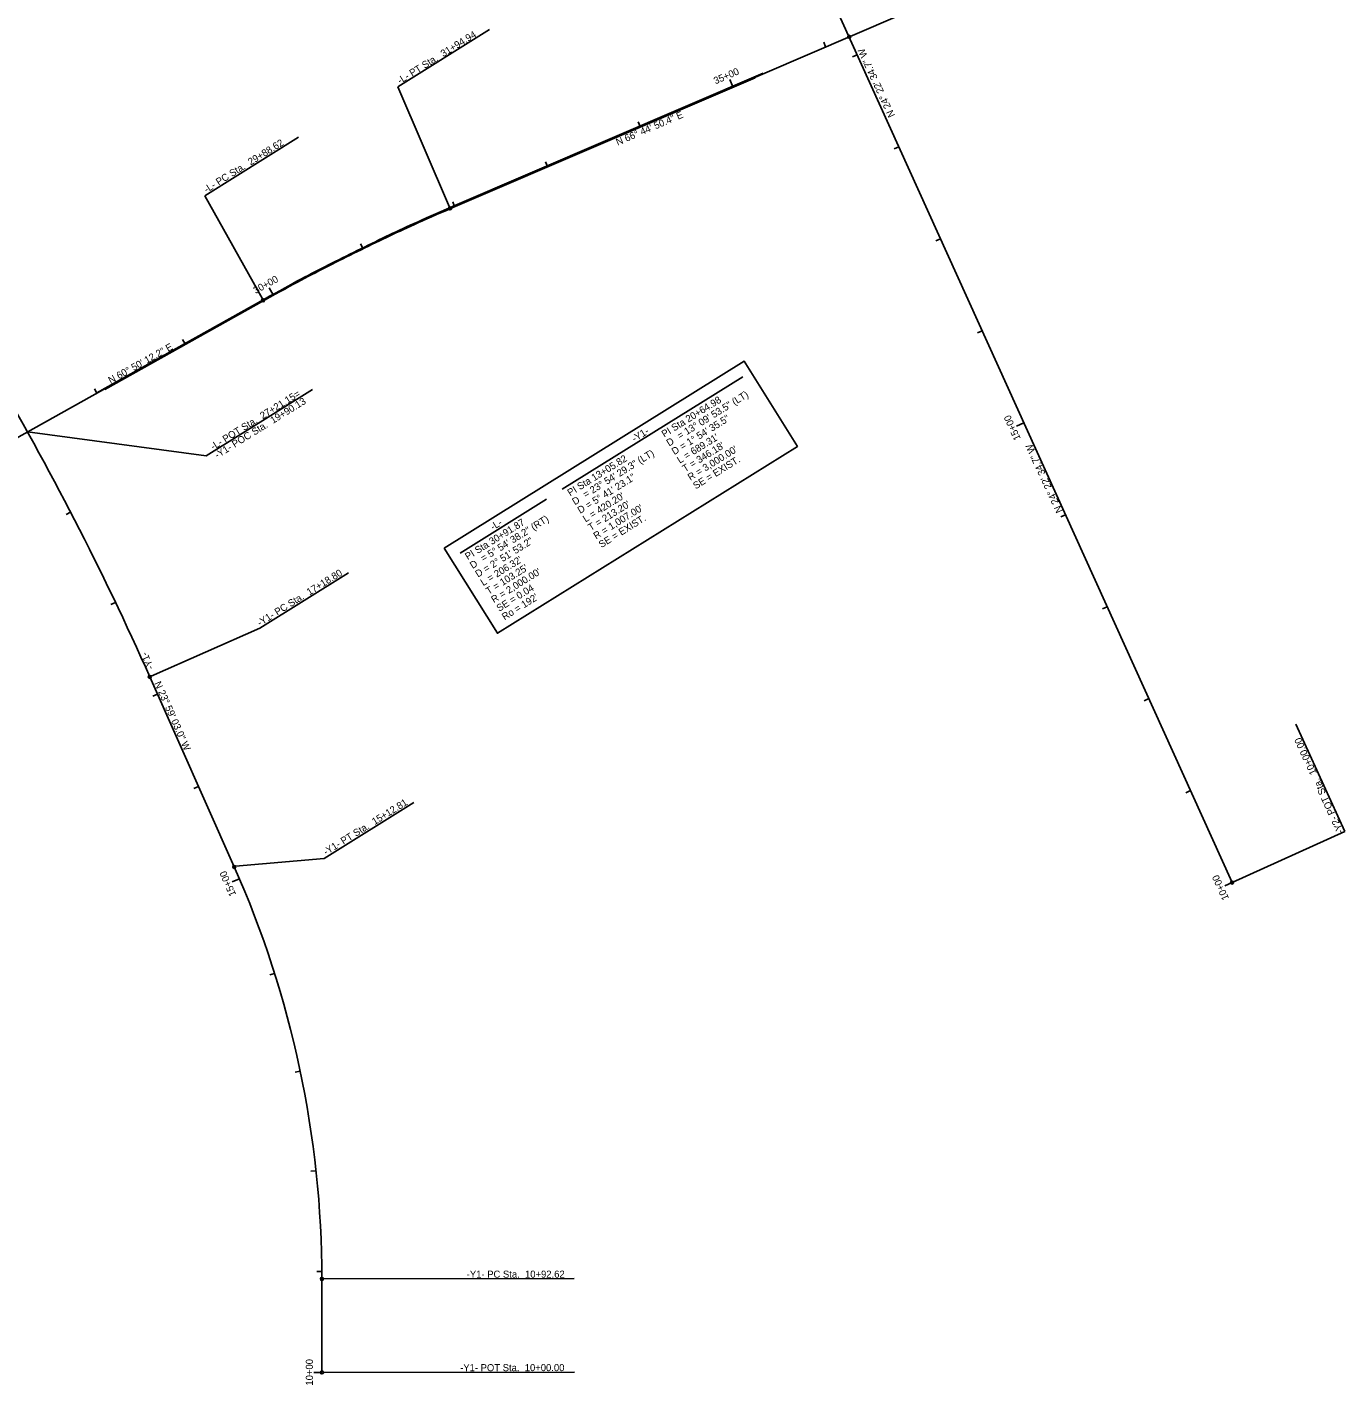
# Model space of a CAD drawing. Extents: x 2045940 to 2048976, y 757914 to 760106.
# Drawn here: x 2047500 to 2048806, y 757914 to 759259 of the extents above; entities that cross this region are included whole.
import ezdxf

# ---------------------------------------------------------------- set-up
doc = ezdxf.new("R2010")
doc.units = 0
for name, color, linetype in [('Prop AutoTurn Projected Path', 7, 'Continuous'), ('Prop Conc 1ft 6in Curb and Gutter', 7, 'Continuous'), ('Prop Conc 5in Monolithic Surface Mount Island', 7, 'Continuous'), ('Prop Dimension', 7, 'Continuous'), ('Prop Horizontal Alignment', 7, 'Continuous'), ('Prop Lane Lines', 7, 'Continuous'), ('Prop Superelevation  Arrow CELL', 7, 'Continuous'), ('Prop Superelevation Label', 7, 'Continuous'), ('Prop Terminator CELL', 7, 'Continuous'), ('Typical Terminator CELL', 7, 'Continuous')]:
    doc.layers.add(name, color=color, linetype=linetype)

msp = doc.modelspace()

# ---------------------------------------------------------------- linework, layer by layer
at = {"layer": 'Prop AutoTurn Projected Path'}
for p, q in [((2048030.6, 758801.4), (2048209.5, 758912.8)), ((2047929.3, 758738.3), (2048014.8, 758791.5))]:
    msp.add_line(p, q, dxfattribs=at)
at = {"layer": 'Prop Conc 1ft 6in Curb and Gutter'}
for p, q in [((2047867.5, 759200.1), (2047958.6, 759256.8)), ((2047918.7, 759081), (2047867.5, 759200.1)), ((2047676.4, 759092.2), (2047769.4, 759150.1)), ((2047733.5, 758989.9), (2047676.4, 759092.2)), ((2047677.9, 758834.6), (2047783.1, 758900.1)), ((2047677.9, 758834.6), (2047500.7, 758858.2)), ((2047730.8, 758664), (2047818.7, 758718.7)), ((2047623.3, 758616.2), (2047730.8, 758664)), ((2048805.8, 758462.5), (2048757.1, 758568.8)), ((2047794.7, 758435.9), (2047883.6, 758491.3)), ((2048694.1, 758411.9), (2048805.8, 758462.5)), ((2047707, 758428), (2047794.7, 758435.9)), ((2047793.9, 758019.3), (2048042.4, 758019.6)), ((2047794, 757926.7), (2048042.5, 757927))]:
    msp.add_line(p, q, dxfattribs=at)
for centre in [(2048314.8, 759249.6), (2047919.3, 759079.6), (2047734.2, 758988.6), (2047621.9, 758615.6), (2047705.6, 758427.4), (2048694.1, 758411.9), (2048694.1, 758411.9), (2047792.4, 758019.3), (2047792.5, 757926.7)]:
    msp.add_circle(centre, 1.5, dxfattribs=at)
at = {"layer": 'Prop Dimension'}
for p, q in [((2048199.6, 759200.1), (2048196.4, 759207.4)), ((2047744.2, 758994.1), (2047740.3, 759001.1)), ((2048487.7, 758867.3), (2048480.4, 758864)), ((2047710.7, 758415.6), (2047703.4, 758412.5)), ((2048694.1, 758411.9), (2048686.8, 758408.6)), ((2047792.5, 757926.7), (2047784.5, 757926.7))]:
    msp.add_line(p, q, dxfattribs=at)
at = {"layer": 'Prop Horizontal Alignment'}
for p, q in [((2048694.1, 758411.9), (2048082.8, 759761)), ((2047919.3, 759079.6), (2048475.2, 759318.5)), ((2047322, 758758.5), (2047734.2, 758988.6)), ((2047705.6, 758427.4), (2047621.9, 758615.6)), ((2047705.6, 758427.4), (2047621.9, 758615.6)), ((2047792.5, 757926.7), (2047792.4, 758019.3)), ((2047792.5, 757926.7), (2047792.4, 758019.3))]:
    msp.add_line(p, q, dxfattribs=at)
for centre, radius, start, end in [((2044880.6, 757397.1), 3000, 23.9646, 37.1294), ((2044880.6, 757397.1), 3000, 23.9646, 37.1294), ((2048708.8, 757242.1), 2000, 113.2527, 119.1633), ((2046785.4, 758018.4), 1007, 0.0564, 23.9646), ((2046785.4, 758018.4), 1007, 0.0564, 23.9646)]:
    msp.add_arc(centre, radius, start, end, dxfattribs=at)
at = {"layer": 'Prop Superelevation  Arrow CELL'}
for p, q in [((2047921.8, 759081.4), (2048229.4, 759213.5)), ((2047569.4, 758896.9), (2047735, 758989.5))]:
    msp.add_line(p, q, dxfattribs=at)
msp.add_open_spline([(2047735, 758989.5), (2047765.4, 759006.4), (2047796.1, 759022.5), (2047858.4, 759053.2), (2047889.9, 759067.7), (2047921.8, 759081.4)], degree=3, dxfattribs=at)
at = {"layer": 'Prop Superelevation Label'}
msp.add_lwpolyline([(2047913.7, 758743.2), (2048210.9, 758928.3), (2048263.5, 758843.9), (2047966.3, 758658.8)], close=True, dxfattribs=at)
at = {"layer": 'Prop Terminator CELL'}
for p, q in [((2048291.4, 759239.6), (2048289.5, 759244.1)), ((2048322.6, 759231.7), (2048318.1, 759229.6)), ((2048107.7, 759160.6), (2048105.7, 759165.2)), ((2048363.9, 759140.6), (2048359.3, 759138.5)), ((2048015.8, 759121.1), (2048013.8, 759125.7)), ((2047923.9, 759081.6), (2047922, 759086.2)), ((2048405.2, 759049.5), (2048400.6, 759047.4)), ((2047833, 759040.1), (2047830.8, 759044.6)), ((2048446.4, 758958.4), (2048441.9, 758956.3)), ((2047656.9, 758945.4), (2047654.4, 758949.7)), ((2047569.5, 758896.6), (2047567.1, 758901)), ((2047543.4, 758778.9), (2047539, 758776.6)), ((2048529, 758776.2), (2048524.4, 758774.2)), ((2047588, 758689.3), (2047583.4, 758687.2)), ((2048570.2, 758685.1), (2048565.7, 758683.1)), ((2047629.6, 758598.4), (2047625, 758596.4)), ((2048611.5, 758594.1), (2048607, 758592)), ((2047670.2, 758507), (2047665.6, 758505)), ((2048652.8, 758503), (2048648.2, 758500.9)), ((2047745.6, 758321.9), (2047740.8, 758320.4)), ((2047770.9, 758225.2), (2047766, 758224.2)), ((2047786.6, 758126.5), (2047781.6, 758126)), ((2047792.4, 758026.7), (2047787.4, 758026.7))]:
    msp.add_line(p, q, dxfattribs=at)
at = {"layer": 'Typical Terminator CELL'}
for p, q in [((2047922.2, 759080.5), (2048221.5, 759209)), ((2047577.5, 758900.3), (2047735.5, 758988.6))]:
    msp.add_line(p, q, dxfattribs=at)
msp.add_open_spline([(2047735.5, 758988.6), (2047765.8, 759005.5), (2047796.6, 759021.7), (2047858.8, 759052.3), (2047890.3, 759066.8), (2047922.2, 759080.5)], degree=3, dxfattribs=at)

# ---------------------------------------------------------------- texts
at = {"layer": 'Prop AutoTurn Projected Path'}
for s, rotation, p in [('= 13%%d 09\' 53.5" (LT)', 31.9183, (2048147.1, 758850.7)), ('PI Sta 20+64.98', 31.9183, (2048131.6, 758852.5)), ('D = 1%%d 54\' 35.5"', 31.9183, (2048141.6, 758835.2)), ('-Y1-', 31.9194, (2048102.1, 758847.9)), ('D', 31.9183, (2048136.4, 758843.7)), ("L = 689.31'", 31.9183, (2048146.9, 758826.7)), ("T = 346.18'", 31.9183, (2048152.2, 758818.2)), ("R = 3,000.00'", 31.9183, (2048157.5, 758809.7)), ('PI Sta 13+05.82', 31.9183, (2048038.3, 758794.4)), ('= 23%%d 54\' 29.3" (LT)', 31.9183, (2048053.7, 758792.6)), ('SE = EXIST.', 31.9194, (2048162.8, 758801.2)), ('D = 5%%d 41\' 23.1"', 31.9183, (2048048.3, 758777)), ('D', 31.9183, (2048043, 758785.5)), ("L = 420.20'", 31.9183, (2048053.6, 758768.5)), ("T = 213.20'", 31.9183, (2048058.8, 758760)), ("R = 1,007.00'", 31.9183, (2048064.1, 758751.6)), ('PI Sta 30+91.87', 31.9194, (2047936.9, 758731.2)), ('= 5%%d 54\' 38.2" (RT)', 31.9194, (2047952.4, 758729.4)), ('-L-', 31.9194, (2047962, 758760.6)), ('SE = EXIST.', 31.9194, (2048069.4, 758743.1)), ('D = 2%%d 51\' 53.2"', 31.9194, (2047947, 758713.9)), ('D', 31.9194, (2047941.7, 758722.4)), ("L = 206.32'", 31.9194, (2047952.2, 758705.4)), ("T = 103.25'", 31.9194, (2047957.5, 758696.9)), ("R = 2,000.00'", 31.9194, (2047962.8, 758688.5)), ('SE = 0.04', 31.9194, (2047968.1, 758680)), ("Ro = 192'", 31.9194, (2047973.4, 758671.5))]:
    msp.add_text(s, height=7, rotation=rotation, dxfattribs=at).set_placement(p)
at = {"layer": 'Prop Conc 1ft 6in Curb and Gutter'}
for s, rotation, p in [('-L- PT Sta.  31+94.94', 31.9194, (2047869.9, 759202.6)), ('-L- PC Sta.  29+88.62', 31.9194, (2047678.2, 759094.8)), ('-L- POT Sta.  27+21.15=', 31.9109, (2047684.8, 758840.1)), ('-Y1- POC Sta.  19+90.13', 31.9109, (2047688.8, 758831.7)), ('-Y1- PC Sta.  17+18.80', 31.9183, (2047731, 758665.5)), ('-Y2- POT Sta.  10+00.00', 114.6102, (2048804.8, 758462.3)), ('-Y1- PT Sta.  15+12.81', 31.9183, (2047796.5, 758438.7)), ('-Y1- PC Sta.  10+92.62', 0.0564, (2047935.9, 758020.5)), ('-Y1- POT Sta.  10+00.00', 0.0564, (2047929.4, 757927.9))]:
    msp.add_text(s, height=7, rotation=rotation, dxfattribs=at).set_placement(p)
at = {"layer": 'Prop Conc 5in Monolithic Surface Mount Island'}
for s, rotation, p in [('35+00', 23.2527, (2048182.3, 759202.4)), ('30+00', 28.8373, (2047726.9, 758994.8)), ('15+00', 114.3763, (2048484.9, 758851.7)), ('-Y1-', 113.2355, (2047626.1, 758624.6)), ('15+00', 113.2355, (2047707.6, 758400)), ('10+00', 114.3763, (2048691.2, 758396.3)), ('10+00', 90.0564, (2047783.5, 757913.7))]:
    msp.add_text(s, height=7, rotation=rotation, dxfattribs=at).set_placement(p)
at = {"layer": 'Prop Lane Lines'}
for s, rotation, p in [('N 24%%d 22\' 34.7" W', 114.7238, (2048360.3, 759171.7)), ('N 66%%d 44\' 50.4" E', 23.2527, (2048085.5, 759141.7)), ('N 60%%d 50\' 12.2" E', 29.1633, (2047583.2, 758905.7)), ('N 24%%d 22\' 34.7" W', 114.7238, (2048526.5, 758779.9)), ('N 23%%d 59\' 03.0" W', 293.9842, (2047626.2, 758609.3))]:
    msp.add_text(s, height=7, rotation=rotation, dxfattribs=at).set_placement(p)

doc.saveas('drawing.dxf')
